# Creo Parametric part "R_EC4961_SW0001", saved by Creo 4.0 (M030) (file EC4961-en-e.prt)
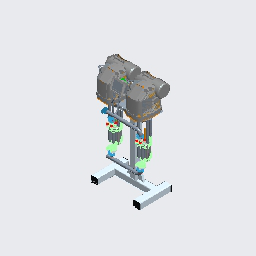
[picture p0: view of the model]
Units: Inch lbm Second (Pro/E Default); INCH, POUND, SECS

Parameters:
  COPY_GEOM_ORIGIN_TYPE = "Part"

Created from: INLBS_PART_SOLID.PRT

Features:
  1. datum plane "RIGHT"
  2. datum plane "TOP"
  3. datum plane "FRONT"
  4. coordinate system
  5. feature "Extern Copy Geom id 40"
  6. feature "Extern Copy Geom id 90"
  7. feature "Extern Copy Geom id 126"
  8. feature "Extern Copy Geom id 162"
  9. feature "Extern Copy Geom id 205"
  10. feature "Extern Copy Geom id 224"
  11. feature "Extern Copy Geom id 243"
  12. feature "Extern Copy Geom id 302"
  13. feature "Extern Copy Geom id 361"
  14. feature "Extern Copy Geom id 413"
  15. feature "Extern Copy Geom id 465"
  16. feature "Extern Copy Geom id 484"
  17. feature "Extern Copy Geom id 495"
  18. feature "Extern Copy Geom id 506"
  19. feature "Extern Copy Geom id 525"
  20. feature "Extern Copy Geom id 544"
  21. feature "Extern Copy Geom id 563"
  22. feature "Extern Copy Geom id 582"
  23. feature "Extern Copy Geom id 601"
  24. feature "Extern Copy Geom id 616"
  25. feature "Extern Copy Geom id 627"
  26. feature "Extern Copy Geom id 638"
  27. feature "Extern Copy Geom id 649"
  28. feature "Extern Copy Geom id 660"
  29. feature "Extern Copy Geom id 671"
  30. feature "Extern Copy Geom id 686"
  31. feature "Extern Copy Geom id 701"
  32. feature "Extern Copy Geom id 720"
  33. feature "Extern Copy Geom id 735"
  34. feature "Extern Copy Geom id 754"
  35. feature "Extern Copy Geom id 773"
  36. feature "Extern Copy Geom id 788"
  37. feature "Extern Copy Geom id 807"
  38. feature "Extern Copy Geom id 826"
  39. feature "Extern Copy Geom id 837"
  40. feature "Extern Copy Geom id 852"
  41. feature "Extern Copy Geom id 867"
  42. feature "Extern Copy Geom id 886"
  43. feature "Extern Copy Geom id 901"
  44. feature "Extern Copy Geom id 920"
  45. feature "Extern Copy Geom id 939"
  46. feature "Extern Copy Geom id 1006"
  47. feature "Extern Copy Geom id 1073"
  48. feature "Extern Copy Geom id 1140"
  49. feature "Extern Copy Geom id 1207"
  50. feature "Extern Copy Geom id 1274"
  51. feature "Extern Copy Geom id 1470"
  52. feature "Extern Copy Geom id 1666"
  53. feature "Extern Copy Geom id 1675"
  54. feature "Extern Copy Geom id 1684"
  55. feature "Extern Copy Geom id 1693"
  56. feature "Extern Copy Geom id 1702"
  57. feature "Extern Copy Geom id 1719"
  58. feature "Extern Copy Geom id 1730"
  59. feature "Extern Copy Geom id 1747"
  60. feature "Extern Copy Geom id 1758"
  61. feature "Extern Copy Geom id 1775"
  62. feature "Extern Copy Geom id 1792"
  63. feature "Extern Copy Geom id 1809"
  64. feature "Extern Copy Geom id 1826"
  65. feature "Extern Copy Geom id 1896"
  66. feature "Extern Copy Geom id 1968"
  67. feature "Extern Copy Geom id 2038"
  68. feature "Extern Copy Geom id 2110"
  69. feature "Extern Copy Geom id 2186"
  70. feature "Extern Copy Geom id 2264"
  71. feature "Extern Copy Geom id 2340"
  72. feature "Extern Copy Geom id 2419"
  73. feature "Extern Copy Geom id 5976"
  74. feature "Extern Copy Geom id 9283"
  75. feature "Extern Copy Geom id 9294"
  76. feature "Extern Copy Geom id 9305"
  77. feature "Extern Copy Geom id 9316"
  78. feature "Extern Copy Geom id 9327"
  79. feature "Extern Copy Geom id 9338"
  80. feature "Extern Copy Geom id 9357"
  81. feature "Extern Copy Geom id 9376"
  82. feature "Extern Copy Geom id 9393"
  83. feature "Extern Copy Geom id 9412"
  84. feature "Extern Copy Geom id 9431"
  85. feature "Extern Copy Geom id 9450"
  86. feature "Extern Copy Geom id 9469"
  87. feature "Extern Copy Geom id 9488"
  88. feature "Extern Copy Geom id 9517"
  89. feature "Extern Copy Geom id 11796"
  90. feature "Extern Copy Geom id 11906"
  91. feature "Extern Copy Geom id 12043"
  92. feature "Extern Copy Geom id 12098"
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
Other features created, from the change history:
  feature "Extern Copy Geom id 12156"
  feature "Extern Copy Geom id 12294"
  feature "Extern Copy Geom id 12432"
  feature "Extern Copy Geom id 12449"
  feature "Extern Copy Geom id 12468"
  feature "Extern Copy Geom id 12487"
  feature "Extern Copy Geom id 12506"
  feature "Extern Copy Geom id 12525"
  feature "Extern Copy Geom id 12544"
  feature "Extern Copy Geom id 12563"
  feature "Extern Copy Geom id 12582"
  feature "Extern Copy Geom id 12601"
  feature "Extern Copy Geom id 12620"
  feature "Extern Copy Geom id 12639"
  feature "Extern Copy Geom id 12656"
  feature "Extern Copy Geom id 12709"
  feature "Extern Copy Geom id 13028"
  feature "Extern Copy Geom id 13039"
  feature "Extern Copy Geom id 13050"
  feature "Extern Copy Geom id 13067"
  feature "Extern Copy Geom id 13078"
  feature "Extern Copy Geom id 13097"
  feature "Extern Copy Geom id 13116"
  feature "Extern Copy Geom id 13135"
  feature "Extern Copy Geom id 13154"
  feature "Extern Copy Geom id 13167"
  feature "Extern Copy Geom id 13244"
  feature "Extern Copy Geom id 14057"
  feature "Extern Copy Geom id 14113"
  feature "Extern Copy Geom id 14127"
  feature "Extern Copy Geom id 14147"
  feature "Extern Copy Geom id 14370"
  feature "Extern Copy Geom id 18788"
  feature "Extern Copy Geom id 18833"
  feature "Extern Copy Geom id 18885"
  feature "Extern Copy Geom id 18928"
  feature "Extern Copy Geom id 18947"
  feature "Extern Copy Geom id 18989"
  feature "Extern Copy Geom id 19211"
  feature "Extern Copy Geom id 21132"
  feature "Extern Copy Geom id 21228"
  feature "Extern Copy Geom id 21267"
  feature "Extern Copy Geom id 21337"
  feature "Extern Copy Geom id 21401"
  feature "Extern Copy Geom id 21439"
  feature "Extern Copy Geom id 21477"
  feature "Extern Copy Geom id 21514"
  feature "Extern Copy Geom id 22109"
  feature "Extern Copy Geom id 22137"
  feature "Extern Copy Geom id 22161"
  feature "Extern Copy Geom id 22185"
  feature "Extern Copy Geom id 22204"
  feature "Extern Copy Geom id 22214"
  feature "Extern Copy Geom id 22224"
  feature "Extern Copy Geom id 22385"
  feature "Extern Copy Geom id 22427"
  feature "Extern Copy Geom id 22447"
  feature "Extern Copy Geom id 22706"
  feature "Extern Copy Geom id 22723"
  feature "Extern Copy Geom id 26280"
  feature "Extern Copy Geom id 29570"
  feature "Extern Copy Geom id 29581"
  feature "Extern Copy Geom id 29598"
  feature "Extern Copy Geom id 29609"
  feature "Extern Copy Geom id 29620"
  feature "Extern Copy Geom id 29637"
  feature "Extern Copy Geom id 29654"
  feature "Extern Copy Geom id 29665"
  feature "Extern Copy Geom id 29676"
  feature "Extern Copy Geom id 29695"
  feature "Extern Copy Geom id 29714"
  feature "Extern Copy Geom id 29731"
  feature "Extern Copy Geom id 29750"
  feature "Extern Copy Geom id 29769"
  feature "Extern Copy Geom id 29788"
  feature "Extern Copy Geom id 29807"
  feature "Extern Copy Geom id 29826"
  feature "Extern Copy Geom id 29855"
  feature "Extern Copy Geom id 32117"
  feature "Extern Copy Geom id 33161"
  feature "Extern Copy Geom id 33298"
  feature "Extern Copy Geom id 33335"
  feature "Extern Copy Geom id 33393"
  feature "Extern Copy Geom id 33552"
  feature "Extern Copy Geom id 33698"
  feature "Extern Copy Geom id 33709"
  feature "Extern Copy Geom id 33728"
  feature "Extern Copy Geom id 33747"
  feature "Extern Copy Geom id 33766"
  feature "Extern Copy Geom id 33785"
  feature "Extern Copy Geom id 33804"
  feature "Extern Copy Geom id 33823"
  feature "Extern Copy Geom id 33842"
  feature "Extern Copy Geom id 33861"
  feature "Extern Copy Geom id 33880"
  feature "Extern Copy Geom id 33899"
  feature "Extern Copy Geom id 33916"
  feature "Extern Copy Geom id 33969"
  feature "Extern Copy Geom id 34291"
  feature "Extern Copy Geom id 34310"
  feature "Extern Copy Geom id 34329"
  feature "Extern Copy Geom id 34348"
  feature "Extern Copy Geom id 34367"
  feature "Extern Copy Geom id 34380"
  feature "Extern Copy Geom id 34457"
  feature "Extern Copy Geom id 35245"
  feature "Extern Copy Geom id 35301"
  feature "Extern Copy Geom id 35315"
  feature "Extern Copy Geom id 35335"
  feature "Extern Copy Geom id 35558"
  feature "Extern Copy Geom id 39969"
  feature "Extern Copy Geom id 40002"
  feature "Extern Copy Geom id 40054"
  feature "Extern Copy Geom id 40097"
  feature "Extern Copy Geom id 40116"
  feature "Extern Copy Geom id 40144"
  feature "Extern Copy Geom id 40369"
  feature "Extern Copy Geom id 42268"
  feature "Extern Copy Geom id 42364"
  feature "Extern Copy Geom id 42415"
  feature "Extern Copy Geom id 42485"
  feature "Extern Copy Geom id 42549"
  feature "Extern Copy Geom id 42587"
  feature "Extern Copy Geom id 42625"
  feature "Extern Copy Geom id 42662"
  feature "Extern Copy Geom id 43257"
  feature "Extern Copy Geom id 43285"
  feature "Extern Copy Geom id 43309"
  feature "Extern Copy Geom id 43333"
  feature "Extern Copy Geom id 43352"
  feature "Extern Copy Geom id 43362"
  feature "Extern Copy Geom id 43384"
  feature "Extern Copy Geom id 43545"
  feature "Extern Copy Geom id 43587"
  feature "Extern Copy Geom id 43607"
  feature "Extern Copy Geom id 43866"
  feature "Extern Copy Geom id 43883"
  feature "Extern Copy Geom id 43900"
  feature "Extern Copy Geom id 43917"
  feature "Extern Copy Geom id 43934"
  feature "Extern Copy Geom id 43993"
  feature "Extern Copy Geom id 44052"
  feature "Extern Copy Geom id 44113"
  feature "Extern Copy Geom id 44172"
  feature "Extern Copy Geom id 44183"
  feature "Extern Copy Geom id 44200"
  feature "Extern Copy Geom id 44211"
  feature "Extern Copy Geom id 44228"
  feature "Extern Copy Geom id 44287"
  feature "Extern Copy Geom id 44346"
  feature "Extern Copy Geom id 44407"
  feature "Extern Copy Geom id 44466"
  feature "Extern Copy Geom id 44513"
  feature "Extern Copy Geom id 44560"
  feature "Extern Copy Geom id 44607"
  feature "Extern Copy Geom id 44654"
  feature "Extern Copy Geom id 44701"
  feature "Extern Copy Geom id 44748"
  feature "Extern Copy Geom id 44853"
  feature "Extern Copy Geom id 45631"
  feature "Extern Copy Geom id 46934"
  feature "Extern Copy Geom id 46951"
  feature "Extern Copy Geom id 46968"
  feature "Extern Copy Geom id 46985"
  feature "Extern Copy Geom id 47065"
  feature "Extern Copy Geom id 47145"
  feature "Extern Copy Geom id 47225"
  feature "Extern Copy Geom id 47326"
  feature "Extern Copy Geom id 47402"
  feature "Extern Copy Geom id 47416"
  feature "Extern Copy Geom id 47430"
  feature "Extern Copy Geom id 47510"
  feature "Extern Copy Geom id 48019"
  feature "Extern Copy Geom id 48579"
  feature "Extern Copy Geom id 48588"
  feature "Extern Copy Geom id 48602"
  feature "Extern Copy Geom id 48616"
  feature "Extern Copy Geom id 48630"
  feature "Extern Copy Geom id 48644"
  feature "Extern Copy Geom id 48658"
  feature "Extern Copy Geom id 48672"
  feature "Extern Copy Geom id 48686"
  feature "Extern Copy Geom id 48705"
  feature "Extern Copy Geom id 48715"
  feature "Extern Copy Geom id 48725"
  feature "Extern Copy Geom id 48785"
  feature "Extern Copy Geom id 48843"
  feature "Extern Copy Geom id 48903"
  feature "Extern Copy Geom id 48963"
  feature "Extern Copy Geom id 49013"
  feature "Extern Copy Geom id 49063"
  feature "Extern Copy Geom id 49111"
  feature "Extern Copy Geom id 49159"
  feature "Extern Copy Geom id 49173"
  feature "Extern Copy Geom id 49273"
  feature "Extern Copy Geom id 50044"
  feature "Extern Copy Geom id 51380"
  feature "Extern Copy Geom id 51397"
  feature "Extern Copy Geom id 51414"
  feature "Extern Copy Geom id 51425"
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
